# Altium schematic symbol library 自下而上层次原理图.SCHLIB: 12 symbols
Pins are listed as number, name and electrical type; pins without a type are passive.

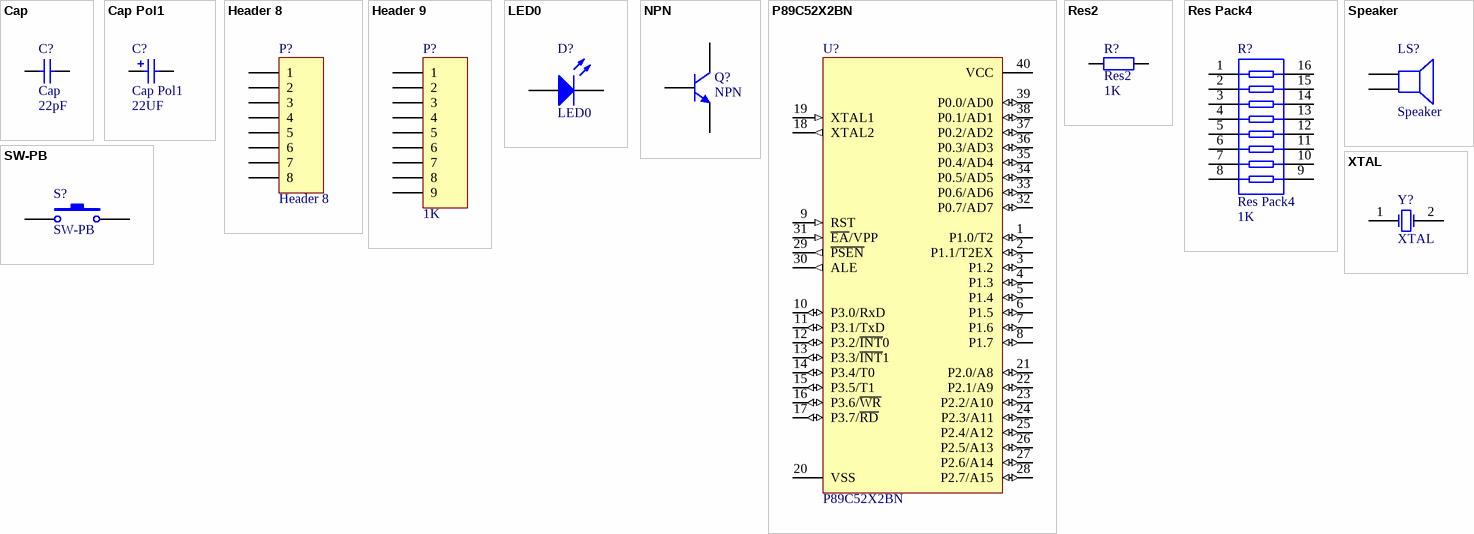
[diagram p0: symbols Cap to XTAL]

## Cap
designator C?  value 22pF
Capacitor
footprint RAD-0.3 (Radial Cap, Thru-Hole; 2 Leads; 0.3 in Pin Spacing)
simulation model CAP (Capacitor)
signal-integrity model Cap
pins: 1, 2

## Cap Pol1
designator C?  value 22UF
Polarized Capacitor (Radial)
footprint RB7.6-15 (Polarized Capacitor (Radial); 2 Leads)
simulation model CAP (Capacitor)
signal-integrity model Cap Pol
pins: 1, 2
1 alternate drawing of the same symbol

## Header 8
designator P?
Header, 8-Pin
footprint HDR1X8 (Connector; Header; 8 Position)
signal-integrity model Connector
pins: 1, 2, 3, 4, 5, 6, 7, 8

## Header 9
designator P?, comment 1K
Header, 9-Pin
footprint HDR1X9 (Connector; Header; 9 Position)
signal-integrity model Connector
pins: 1, 2, 3, 4, 5, 6, 7, 8, 9

## LED0
designator D?
Typical INFRARED GaAs LED
footprint LED-0 (LED; 2 Leads)
simulation model LED0 (Diode)
pins: 1 A, 2 K

## NPN
designator Q?
NPN Bipolar Transistor
footprint TO-226-AA (TO, Flat Index; 3 In-Line, Axial Leads; Body Dia. 4.8mm; Leads 0.55 x 0.51 mm (max))
simulation model NPN
signal-integrity model NPN
pins: 1 C, 2 B, 3 E

## P89C52X2BN
designator U?
80C51 8-Bit Flash Microcontroller Family, 8 kB Flash; Package Information: Latest Revision: Aug-2000; Code - JEDEC: MO-015
footprint DIP40 (DIP; 40 Leads; Row Spacing 15.24 mm; Pitch 2.54 mm)
pins: 1 P1.0/T2 (io), 2 P1.1/T2EX (io), 3 P1.2 (io), 4 P1.3 (io), 5 P1.4 (io), 6 P1.5 (io), 7 P1.6 (io), 8 P1.7 (io), 9 RST (in), 10 P3.0/RxD (io), 11 P3.1/TxD (io), 12 P3.2/~{INT}0 (io), 13 P3.3/~{INT}1 (io), 14 P3.4/T0 (io), 15 P3.5/T1 (io), 16 P3.6/~{WR} (io), 17 P3.7/~{RD} (io), 18 XTAL2 (out), 19 XTAL1 (in), 20 VSS (power), 21 P2.0/A8 (io), 22 P2.1/A9 (io), 23 P2.2/A10 (io), 24 P2.3/A11 (io), 25 P2.4/A12 (io), 26 P2.5/A13 (io), 27 P2.6/A14 (io), 28 P2.7/A15 (io), 29 ~{PSEN} (out), 30 ALE (out), 31 ~{EA}/VPP (in), 32 P0.7/AD7 (io), 33 P0.6/AD6 (io), 34 P0.5/AD5 (io), 35 P0.4/AD4 (io), 36 P0.3/AD3 (io), 37 P0.2/AD2 (io), 38 P0.1/AD1 (io), 39 P0.0/AD0 (io), 40 VCC (power)

## Res2
designator R?  value 1K
Resistor
footprint AXIAL-0.4 (Axial Device, Thru-Hole; 2 Leads; 0.4 in Pin Spacing)
simulation model RESISTOR (Resistor)
signal-integrity model Res
pins: 1, 2

## Res Pack4
designator R?  value 1K
Isolated Resistor Network
footprint DIP-16 (DIP; 16 Leads; Row Spacing 7.62 mm; Pitch 2.54 mm)
footprint SSOP16_L (SOP, 16-Leads, Body 6.2x5.3mm, Pitch 0.65mm, IPC High Density)
footprint SSOP16_M (SOP, 16-Leads, Body 6.2x5.3mm, Pitch 0.65mm, IPC Low Density)
simulation model respack_8 (Spice Subcircuit)
pins: 1, 2, 3, 4, 5, 6, 7, 8, 9, 10, 11, 12, 13, 14, 15, 16

## Speaker
designator LS?
Loudspeaker
footprint PIN2 (Loudspeaker; 2 Leads)
pins: 1, 2

## SW-PB
designator S?
Switch
footprint SPST-2 (Switch; 2 Leads)
pins: 1, 2

## XTAL
designator Y?
Crystal Oscillator
footprint R38 (Crystal, Thru-Hole; 2 Leads; Body 3.1 x 8.2 mm (Dia.xH))
simulation model XTAL (Spice Subcircuit)
pins: 1 OSC1, 2 OSC2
